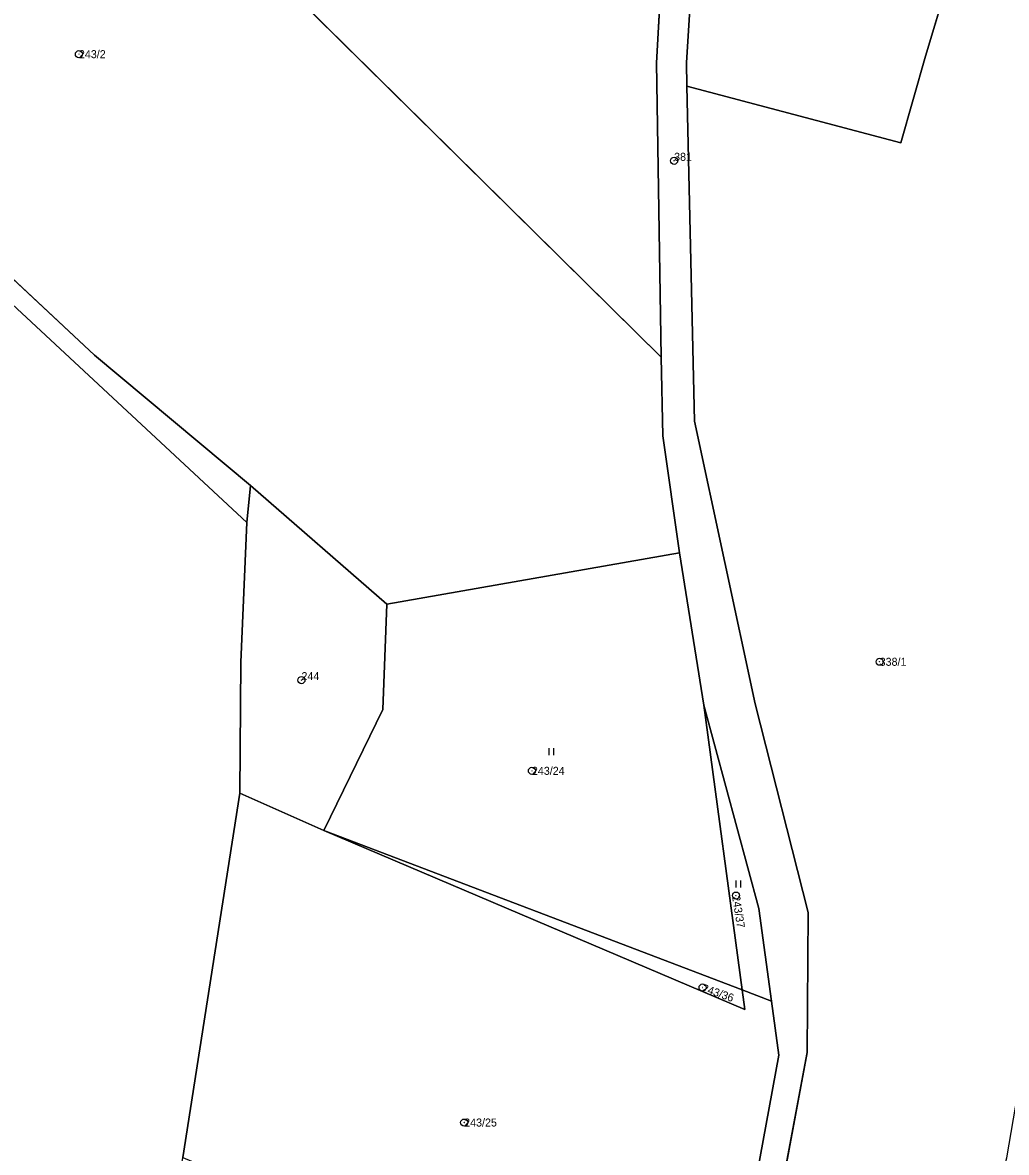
# Model space of a CAD drawing. Extents: x -652854 to -650068, y -1097661 to -1095417.
# Drawn here: x -650819.6 to -650610.6, y -1096498.9 to -1096258.8 of the extents above; entities that cross this region are included whole.
import ezdxf

# ---------------------------------------------------------------- set-up
doc = ezdxf.new("R2010")
doc.units = 0
for name, color, linetype in [('Definiční body parcel', 7, 'Continuous'), ('Hranice parcel', 7, 'Continuous'), ('Obvody jako plochy', 7, 'Continuous'), ('Parcelní čísla', 7, 'Continuous'), ('Značky kultur', 7, 'Continuous')]:
    doc.layers.add(name, color=color, linetype=linetype)

msp = doc.modelspace()

# ---------------------------------------------------------------- linework, layer by layer
at = {"layer": 'Definiční body parcel'}
for centre, radius in [((-650807.63, -1096265.53), 0.75), ((-650807.63, -1096265.53), 0.0327), ((-650681.18, -1096288.19), 0.75), ((-650681.18, -1096288.19), 0.0327), ((-650637.51, -1096394.64), 0.75), ((-650637.51, -1096394.64), 0.0327), ((-650760.35, -1096398.54), 0.75), ((-650760.35, -1096398.54), 0.0327), ((-650711.39, -1096417.81), 0.75), ((-650711.39, -1096417.81), 0.0327), ((-650668.04, -1096444.31), 0.75), ((-650668.04, -1096444.31), 0.0327), ((-650675.14, -1096463.85), 0.75), ((-650675.14, -1096463.85), 0.0327), ((-650725.78, -1096492.54), 0.75), ((-650725.78, -1096492.54), 0.0327)]:
    msp.add_circle(centre, radius, dxfattribs=at)
at = {"layer": 'Hranice parcel'}
for p, q in [((-650615.39, -1096224.69), (-650627.74, -1096265.94)), ((-650682.55, -1096225.39), (-650684.92, -1096267.36)), ((-650676.11, -1096228.76), (-650678.58, -1096267.28)), ((-650683.93, -1096329.93), (-650773.22, -1096241.73)), ((-650684.92, -1096267.36), (-650683.93, -1096329.93)), ((-650678.58, -1096267.28), (-650678.51, -1096272.34)), ((-650627.74, -1096265.94), (-650633.03, -1096284.37)), ((-650678.51, -1096272.34), (-650676.87, -1096343.5)), ((-650633.03, -1096284.37), (-650678.51, -1096272.34)), ((-650804.31, -1096329.49), (-650835.17, -1096300.67)), ((-650771.95, -1096365.02), (-650824.93, -1096315.79)), ((-650771.2, -1096357.19), (-650804.31, -1096329.49)), ((-650683.93, -1096329.93), (-650683.6, -1096346.64)), ((-650676.87, -1096343.5), (-650663.97, -1096403.54)), ((-650683.6, -1096346.64), (-650680.01, -1096371.46)), ((-650771.95, -1096365.02), (-650771.2, -1096357.19)), ((-650771.2, -1096357.19), (-650742.24, -1096382.41)), ((-650773.25, -1096394.71), (-650771.95, -1096365.02)), ((-650742.24, -1096382.41), (-650680.01, -1096371.46)), ((-650680.01, -1096371.46), (-650674.86, -1096403.86)), ((-650743.07, -1096404.78), (-650742.24, -1096382.41)), ((-650773.41, -1096422.59), (-650773.25, -1096394.71)), ((-650755.6, -1096430.5), (-650743.07, -1096404.78)), ((-650666.75, -1096464.34), (-650674.86, -1096403.86)), ((-650674.86, -1096403.86), (-650663.17, -1096447.09)), ((-650663.97, -1096403.54), (-650652.67, -1096447.91)), ((-650785.54, -1096499.95), (-650773.41, -1096422.59)), ((-650773.41, -1096422.59), (-650755.6, -1096430.5)), ((-650755.6, -1096430.5), (-650666.17, -1096468.53)), ((-650755.6, -1096430.5), (-650666.75, -1096464.34)), ((-650663.17, -1096447.09), (-650660.51, -1096466.72)), ((-650652.67, -1096447.91), (-650652.9, -1096477.63)), ((-650666.75, -1096464.34), (-650660.51, -1096466.72)), ((-650666.17, -1096468.53), (-650666.75, -1096464.34)), ((-650660.51, -1096466.72), (-650658.91, -1096478.22)), ((-650652.9, -1096477.63), (-650668.72, -1096561.85)), ((-650658.91, -1096478.22), (-650664.97, -1096511.01))]:
    msp.add_line(p, q, dxfattribs=at)
at = {"layer": 'Obvody jako plochy'}
for points in [[(-650683.93, -1096329.93), (-650684.92, -1096267.36), (-650682.55, -1096225.39), (-650668.72, -1096197.09), (-650711.09, -1096192.09), (-650728.33, -1096188.58), (-650742.01, -1096181.85), (-650751.15, -1096173.61), (-650769.16, -1096151.85), (-650788.5, -1096124.42), (-650836.01, -1096073.17), (-650848.76, -1096104.66), (-650859.75, -1096135.85), (-650864.8, -1096149.44), (-650773.22, -1096241.73)], [(-650683.6, -1096346.64), (-650683.93, -1096329.93), (-650773.22, -1096241.73), (-650864.8, -1096149.44), (-650869.04, -1096160.72), (-650895.79, -1096238.76), (-650877.55, -1096258.47), (-650835.17, -1096300.67), (-650804.31, -1096329.49), (-650771.2, -1096357.19), (-650742.24, -1096382.41), (-650680.01, -1096371.46)], [(-650771.2, -1096357.19), (-650804.31, -1096329.49), (-650835.17, -1096300.67), (-650877.55, -1096258.47), (-650895.79, -1096238.76), (-650898.03, -1096236.26), (-650924.83, -1096207.12), (-650925.77, -1096197.7), (-650930.11, -1096207.71), (-650879, -1096263.35), (-650824.93, -1096315.79), (-650771.95, -1096365.02)], [(-650673.79, -1096218.72), (-650676.11, -1096228.76), (-650678.58, -1096267.28), (-650678.51, -1096272.34), (-650633.03, -1096284.37), (-650627.74, -1096265.94), (-650615.39, -1096224.69), (-650610.66, -1096208.54), (-650628.94, -1096201.29), (-650636.64, -1096200.47), (-650659.23, -1096205.31), (-650665.46, -1096202.7)], [(-650615.39, -1096224.69), (-650627.74, -1096265.94), (-650633.03, -1096284.37), (-650678.51, -1096272.34), (-650676.87, -1096343.5), (-650663.97, -1096403.54), (-650652.67, -1096447.91), (-650652.9, -1096477.63), (-650668.72, -1096561.85), (-650683.81, -1096604.11), (-650656.55, -1096618.34), (-650641.96, -1096600.14), (-650628.48, -1096567.58), (-650610.51, -1096500.05), (-650598.36, -1096429.24), (-650603.36, -1096390.83), (-650603.97, -1096349.81), (-650597.72, -1096321.86), (-650593.22, -1096283.03), (-650569.84, -1096224.92), (-650587.51, -1096217.28), (-650610.66, -1096208.54)], [(-650799.85, -1096650.9), (-650801.47, -1096660.7), (-650795.97, -1096647.36), (-650807.31, -1096617.17), (-650798.99, -1096582.65), (-650793.31, -1096549.53), (-650785.54, -1096499.95), (-650773.41, -1096422.59), (-650773.25, -1096394.71), (-650771.95, -1096365.02), (-650824.93, -1096315.79), (-650882.2, -1096467.08), (-650940.33, -1096616.41), (-650895.72, -1096750.97), (-650857.12, -1096867.39), (-650851.23, -1096836.35), (-650839.76, -1096776.84), (-650837.51, -1096768.15), (-650819.95, -1096709.68), (-650802.47, -1096650.3)], [(-650771.2, -1096357.19), (-650771.95, -1096365.02), (-650773.25, -1096394.71), (-650773.41, -1096422.59), (-650755.6, -1096430.5), (-650743.07, -1096404.78), (-650742.24, -1096382.41)], [(-650680.01, -1096371.46), (-650742.24, -1096382.41), (-650743.07, -1096404.78), (-650755.6, -1096430.5), (-650666.75, -1096464.34), (-650674.86, -1096403.86)], [(-650674.86, -1096403.86), (-650666.75, -1096464.34), (-650660.51, -1096466.72), (-650663.17, -1096447.09)], [(-650664.97, -1096511.01), (-650658.91, -1096478.22), (-650660.51, -1096466.72), (-650666.75, -1096464.34), (-650666.17, -1096468.53), (-650755.6, -1096430.5), (-650773.41, -1096422.59), (-650785.54, -1096499.95), (-650671.73, -1096547.95)], [(-650755.6, -1096430.5), (-650666.17, -1096468.53), (-650666.75, -1096464.34)]]:
    msp.add_lwpolyline(points, close=True, dxfattribs=at)
msp.add_lwpolyline([(-650668.72, -1096561.85), (-650652.9, -1096477.63), (-650652.67, -1096447.91), (-650663.97, -1096403.54), (-650676.87, -1096343.5), (-650678.51, -1096272.34), (-650678.58, -1096267.28), (-650676.11, -1096228.76), (-650673.79, -1096218.72), (-650665.46, -1096202.7), (-650662.85, -1096197.68), (-650668.72, -1096197.09), (-650682.55, -1096225.39), (-650684.92, -1096267.36), (-650683.93, -1096329.93), (-650683.6, -1096346.64), (-650680.01, -1096371.46), (-650674.86, -1096403.86), (-650663.17, -1096447.09), (-650660.51, -1096466.72), (-650658.91, -1096478.22), (-650664.97, -1096511.01)], dxfattribs=at)
at = {"layer": 'Značky kultur'}
for p, q in [((-650707.787, -1096412.975), (-650707.787, -1096414.475)), ((-650706.765, -1096414.475), (-650706.765, -1096412.975)), ((-650668.057, -1096441.105), (-650668.057, -1096442.605)), ((-650667.035, -1096442.605), (-650667.035, -1096441.105))]:
    msp.add_line(p, q, dxfattribs=at)

# ---------------------------------------------------------------- texts
at = {"layer": 'Parcelní čísla'}
for s, p in [('243/2', (-650807.63, -1096266.38)), ('381', (-650681.18, -1096288.19)), ('338/1', (-650637.51, -1096395.49)), ('244', (-650760.35, -1096398.54)), ('243/24', (-650711.39, -1096418.66)), ('243/25', (-650725.78, -1096493.39))]:
    msp.add_text(s, height=1.7, dxfattribs=at).set_placement(p)
for s, rotation, p in [('243/37', 279.027, (-650668.879, -1096444.443)), ('243/36', 340.731, (-650675.421, -1096464.652))]:
    msp.add_text(s, height=1.7, rotation=rotation, dxfattribs=at).set_placement(p)

doc.saveas('drawing.dxf')
